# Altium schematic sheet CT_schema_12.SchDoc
size 147 x 119 mm
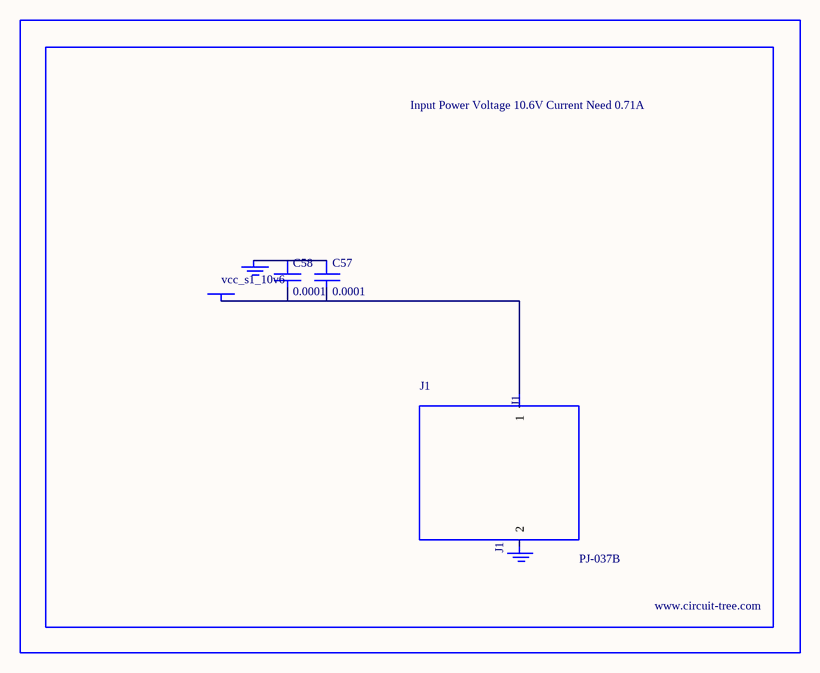
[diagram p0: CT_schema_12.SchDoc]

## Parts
BORDER11  (no value)
C57  0.0001  [EXV-9H]
C58  0.0001  [EXV-9H]
GND_INSTANCE_11_0  (no value)
GND_INSTANCE_11_1  (no value)
J1  PJ-037B  [PJ-037B_PACKAGE]
POWER_INSTANCE_11_0  vcc_s1_10v6

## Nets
NetC57_1: C57.1 C58.1 GND_INSTANCE_11_0.0(GND)
NetC57_2: C57.2 C58.2 J1.1 POWER_INSTANCE_11_0.0(PWR)

Not connected (* = marked no-connect by the designer): GND_INSTANCE_11_1 0(GND); J1 2

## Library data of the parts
BORDER11 = BORDER_PAGE11
C57 C58 = EDK107M035A9HAA
GND_INSTANCE_11_0 GND_INSTANCE_11_1 = GND
POWER_INSTANCE_11_0 = PWR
